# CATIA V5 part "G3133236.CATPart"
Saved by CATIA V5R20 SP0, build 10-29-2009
Part number: G3133236
Revision: 9
Definition: design
Nomenclature: G31332036
Source: made
Description: NOT SPECIFIED
Bounding box of the stored display mesh (mm): x -27 to 36, y -23.329 to 23.329, z -23.5 to 23.5
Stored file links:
  C:\Users\Raffaele\Desktop\3D X SITO CF\BOLEX\24-BUSH REF 313\G3133236.CATPart
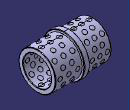
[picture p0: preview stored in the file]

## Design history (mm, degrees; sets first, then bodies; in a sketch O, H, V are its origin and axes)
Body1 "MANIFOLD_SOLID_BREP #11913" (main body)
  Solid1: solid without history
Body2 "MANIFOLD_SOLID_BREP #12068"
  Solid2: solid without history
Body3 "MANIFOLD_SOLID_BREP #12223"
  Solid3: solid without history
Body4 "MANIFOLD_SOLID_BREP #12376"
  Solid4: solid without history
Body5 "MANIFOLD_SOLID_BREP #12533"
  Solid5: solid without history
Body6 "MANIFOLD_SOLID_BREP #12686"
  Solid6: solid without history
Body7 "MANIFOLD_SOLID_BREP #12839"
  Solid7: solid without history
Body8 "MANIFOLD_SOLID_BREP #12996"
  Solid8: solid without history
Body9 "MANIFOLD_SOLID_BREP #13149"
  Solid9: solid without history
Body10 "MANIFOLD_SOLID_BREP #13306"
  Solid10: solid without history
Body11 "MANIFOLD_SOLID_BREP #13463"
  Solid11: solid without history
Body12 "MANIFOLD_SOLID_BREP #13620"
  Solid12: solid without history
Body13 "MANIFOLD_SOLID_BREP #13777"
  Solid13: solid without history
Body14 "MANIFOLD_SOLID_BREP #13934"
  Solid14: solid without history
Body15 "MANIFOLD_SOLID_BREP #14091"
  Solid15: solid without history
Body16 "MANIFOLD_SOLID_BREP #14248"
  Solid16: solid without history
Body17 "MANIFOLD_SOLID_BREP #14405"
  Solid17: solid without history
Body18 "MANIFOLD_SOLID_BREP #14558"
  Solid18: solid without history
Body19 "MANIFOLD_SOLID_BREP #14715"
  Solid19: solid without history
Body20 "MANIFOLD_SOLID_BREP #14868"
  Solid20: solid without history
Body21 "MANIFOLD_SOLID_BREP #15021"
  Solid21: solid without history
Body22 "MANIFOLD_SOLID_BREP #15178"
  Solid22: solid without history
Body23 "MANIFOLD_SOLID_BREP #15331"
  Solid23: solid without history
Body24 "MANIFOLD_SOLID_BREP #15486"
  Solid24: solid without history
Body25 "MANIFOLD_SOLID_BREP #15641"
  Solid25: solid without history
Body26 "MANIFOLD_SOLID_BREP #15794"
  Solid26: solid without history
Body27 "MANIFOLD_SOLID_BREP #15951"
  Solid27: solid without history
Body28 "MANIFOLD_SOLID_BREP #16104"
  Solid28: solid without history
Body29 "MANIFOLD_SOLID_BREP #16257"
  Solid29: solid without history
Body30 "MANIFOLD_SOLID_BREP #16414"
  Solid30: solid without history
Body31 "MANIFOLD_SOLID_BREP #16567"
  Solid31: solid without history
Body32 "MANIFOLD_SOLID_BREP #16722"
  Solid32: solid without history
Body33 "MANIFOLD_SOLID_BREP #16877"
  Solid33: solid without history
Body34 "MANIFOLD_SOLID_BREP #17034"
  Solid34: solid without history
Body35 "MANIFOLD_SOLID_BREP #17191"
  Solid35: solid without history
Body36 "MANIFOLD_SOLID_BREP #17348"
  Solid36: solid without history
Body37 "MANIFOLD_SOLID_BREP #17505"
  Solid37: solid without history
Body38 "MANIFOLD_SOLID_BREP #17662"
  Solid38: solid without history
Body39 "MANIFOLD_SOLID_BREP #17819"
  Solid39: solid without history
Body40 "MANIFOLD_SOLID_BREP #17976"
  Solid40: solid without history
Body41 "MANIFOLD_SOLID_BREP #18133"
  Solid41: solid without history
Body42 "MANIFOLD_SOLID_BREP #18286"
  Solid42: solid without history
Body43 "MANIFOLD_SOLID_BREP #18439"
  Solid43: solid without history
Body44 "MANIFOLD_SOLID_BREP #18592"
  Solid44: solid without history
Body45 "MANIFOLD_SOLID_BREP #18749"
  Solid45: solid without history
Body46 "MANIFOLD_SOLID_BREP #18906"
  Solid46: solid without history
Body47 "MANIFOLD_SOLID_BREP #19063"
  Solid47: solid without history
Body48 "MANIFOLD_SOLID_BREP #19216"
  Solid48: solid without history
Body49 "MANIFOLD_SOLID_BREP #19369"
  Solid49: solid without history
Body50 "MANIFOLD_SOLID_BREP #19522"
  Solid50: solid without history
Body51 "MANIFOLD_SOLID_BREP #19675"
  Solid51: solid without history
Body52 "MANIFOLD_SOLID_BREP #19828"
  Solid52: solid without history
Body53 "MANIFOLD_SOLID_BREP #19981"
  Solid53: solid without history
Body54 "MANIFOLD_SOLID_BREP #20138"
  Solid54: solid without history
Body55 "MANIFOLD_SOLID_BREP #20295"
  Solid55: solid without history
Body56 "MANIFOLD_SOLID_BREP #20452"
  Solid56: solid without history
Body57 "MANIFOLD_SOLID_BREP #20605"
  Solid57: solid without history
Body58 "MANIFOLD_SOLID_BREP #20758"
  Solid58: solid without history
Body59 "MANIFOLD_SOLID_BREP #20911"
  Solid59: solid without history
Body60 "MANIFOLD_SOLID_BREP #21066"
  Solid60: solid without history
Body61 "MANIFOLD_SOLID_BREP #21221"
  Solid61: solid without history
Body62 "MANIFOLD_SOLID_BREP #21376"
  Solid62: solid without history
Body63 "MANIFOLD_SOLID_BREP #21531"
  Solid63: solid without history
Body64 "MANIFOLD_SOLID_BREP #21686"
  Solid64: solid without history
Body65 "MANIFOLD_SOLID_BREP #21841"
  Solid65: solid without history
Body66 "MANIFOLD_SOLID_BREP #21998"
  Solid66: solid without history
Body67 "MANIFOLD_SOLID_BREP #22155"
  Solid67: solid without history
Body68 "MANIFOLD_SOLID_BREP #22312"
  Solid68: solid without history
Body69 "MANIFOLD_SOLID_BREP #22469"
  Solid69: solid without history
Body70 "MANIFOLD_SOLID_BREP #22626"
  Solid70: solid without history
Body71 "MANIFOLD_SOLID_BREP #22783"
  Solid71: solid without history
Body72 "MANIFOLD_SOLID_BREP #22940"
  Solid72: solid without history
Body73 "MANIFOLD_SOLID_BREP #23097"
  Solid73: solid without history
Body74 "MANIFOLD_SOLID_BREP #23254"
  Solid74: solid without history
Body75 "MANIFOLD_SOLID_BREP #23411"
  Solid75: solid without history
Body76 "MANIFOLD_SOLID_BREP #23568"
  Solid76: solid without history
Body77 "MANIFOLD_SOLID_BREP #23725"
  Solid77: solid without history
Body78 "MANIFOLD_SOLID_BREP #23882"
  Solid78: solid without history
Body79 "MANIFOLD_SOLID_BREP #24039"
  Solid79: solid without history
Body80 "MANIFOLD_SOLID_BREP #24196"
  Solid80: solid without history
Body81 "MANIFOLD_SOLID_BREP #24353"
  Solid81: solid without history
